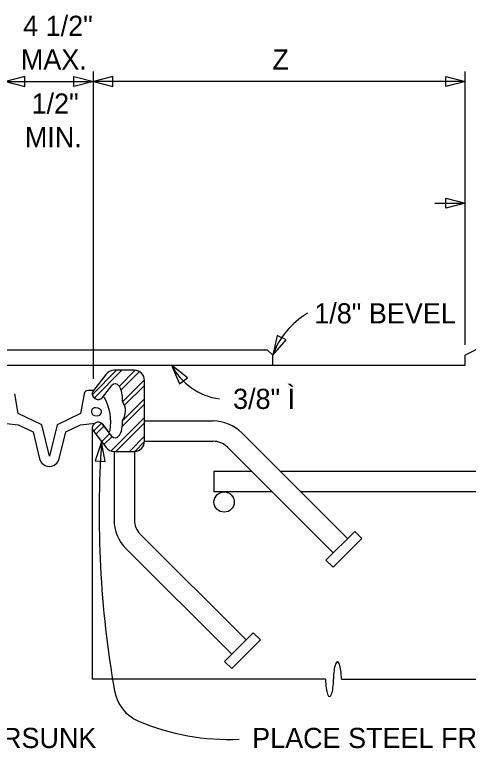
# Model space of a CAD drawing. Extents: x 19590 to 20151, y 19944 to 20103.
# Drawn here: x 19692.57 to 19703.76, y 20061.56 to 20079.66 of the extents above; entities that cross this region are included whole.
import ezdxf

# ---------------------------------------------------------------- set-up
doc = ezdxf.new("R2010")
doc.units = 0
for name, color, linetype in [('DETAIL_PR', 7, 'Continuous'), ('DETAIL_TEXT_DIMEN_PR', 7, 'Continuous'), ('Level 1', 7, 'Continuous')]:
    doc.layers.add(name, color=color, linetype=linetype)

# ---------------------------------------------------------------- blocks, each defined once
blk = doc.blocks.new('BRE')
at = {"layer": 'DETAIL_PR'}
for centre, ratio, start_param, end_param in [((0, 0.098), 0.230206, 4.712389, 7.853982), ((0, -0.098), 0.230204, 1.570796, 4.712389)]:
    blk.add_ellipse(centre, major_axis=(-0.427, 0), ratio=ratio, start_param=start_param, end_param=end_param, dxfattribs=at)

msp = doc.modelspace()

# ---------------------------------------------------------------- linework, layer by layer
at = {"layer": 'DETAIL_PR'}
for p, q in [((19698.811, 20071.384), (19686.436, 20071.384)), ((19698.811, 20071.384), (19686.436, 20071.384)), ((19698.936, 20071.259), (19698.811, 20071.384)), ((19698.936, 20071.259), (19698.811, 20071.384)), ((19704.186, 20071.509), (19703.686, 20071.259)), ((19704.186, 20071.509), (19703.686, 20071.259)), ((19698.936, 20071.009), (19698.936, 20071.259)), ((19698.936, 20071.009), (19698.936, 20071.259)), ((19703.686, 20071.009), (19703.686, 20071.259)), ((19703.686, 20071.009), (19703.686, 20071.259)), ((19686.436, 20071.009), (19698.936, 20071.009)), ((19686.436, 20071.009), (19698.936, 20071.009)), ((19695.444, 20071.009), (19703.686, 20071.009)), ((19695.444, 20071.009), (19703.686, 20071.009)), ((19695.085, 20070.884), (19694.49, 20070.288)), ((19695.085, 20070.884), (19694.49, 20070.288)), ((19695.218, 20070.884), (19694.54, 20070.206)), ((19695.218, 20070.884), (19694.54, 20070.206)), ((19695.526, 20070.884), (19695.026, 20070.884)), ((19695.526, 20070.884), (19695.026, 20070.884)), ((19695.549, 20070.884), (19695.155, 20070.49)), ((19695.549, 20070.884), (19695.155, 20070.49)), ((19695.649, 20070.851), (19695.199, 20070.401)), ((19695.649, 20070.851), (19695.199, 20070.401)), ((19694.828, 20070.787), (19694.515, 20070.384)), ((19694.828, 20070.787), (19694.515, 20070.384)), ((19695.776, 20070.646), (19695.24, 20070.111)), ((19695.776, 20070.646), (19695.24, 20070.111)), ((19694.737, 20070.211), (19694.967, 20070.508)), ((19694.737, 20070.211), (19694.967, 20070.508)), ((19695.776, 20070.513), (19695.284, 20070.021)), ((19695.776, 20070.513), (19695.284, 20070.021)), ((19695.776, 20069.134), (19695.776, 20070.634)), ((19695.776, 20069.134), (19695.776, 20070.634)), ((19692.658, 20069.818), (19692.574, 20070.306)), ((19692.658, 20069.818), (19692.574, 20070.306)), ((19694.285, 20070.306), (19694.201, 20069.818)), ((19694.285, 20070.306), (19694.201, 20069.818)), ((19694.515, 20070.384), (19694.377, 20070.384)), ((19694.515, 20070.384), (19694.377, 20070.384)), ((19694.561, 20070.189), (19694.537, 20070.208)), ((19694.537, 20070.208), (19694.561, 20070.189)), ((19694.561, 20070.189), (19694.537, 20070.208)), ((19694.537, 20070.208), (19694.561, 20070.189)), ((19695.776, 20070.184), (19695.237, 20069.646)), ((19695.776, 20070.184), (19695.237, 20069.646)), ((19694.632, 20069.95), (19694.57, 20069.958)), ((19694.632, 20069.95), (19694.57, 20069.958)), ((19695.776, 20070.052), (19695.231, 20069.507)), ((19695.776, 20070.052), (19695.231, 20069.507)), ((19693.241, 20069.541), (19692.658, 20069.818)), ((19693.241, 20069.541), (19692.658, 20069.818)), ((19694.201, 20069.818), (19693.618, 20069.541)), ((19694.201, 20069.818), (19693.618, 20069.541)), ((19694.545, 20069.772), (19694.607, 20069.764)), ((19694.545, 20069.772), (19694.607, 20069.764)), ((19692.298, 20069.578), (19692.658, 20069.541)), ((19692.298, 20069.578), (19692.658, 20069.541)), ((19694.201, 20069.541), (19694.561, 20069.578)), ((19694.201, 20069.541), (19694.561, 20069.578)), ((19694.711, 20069.581), (19694.514, 20069.384)), ((19694.711, 20069.581), (19694.514, 20069.384)), ((19694.561, 20069.578), (19694.537, 20069.559)), ((19694.561, 20069.578), (19694.537, 20069.559)), ((19695.776, 20069.72), (19694.95, 20068.895)), ((19695.776, 20069.72), (19694.95, 20068.895)), ((19695.776, 20069.588), (19695.072, 20068.884)), ((19695.776, 20069.588), (19695.072, 20068.884)), ((19695.776, 20069.634), (19697.465, 20069.634)), ((19695.776, 20069.634), (19697.465, 20069.634)), ((19692.658, 20069.541), (19693.026, 20069.366)), ((19692.658, 20069.541), (19693.026, 20069.366)), ((19693.429, 20068.762), (19693.241, 20069.541)), ((19693.429, 20068.762), (19693.241, 20069.541)), ((19693.618, 20069.541), (19693.429, 20068.762)), ((19693.618, 20069.541), (19693.429, 20068.762)), ((19693.833, 20069.366), (19694.201, 20069.541)), ((19693.833, 20069.366), (19694.201, 20069.541)), ((19694.488, 20069.454), (19694.488, 20063.262)), ((19694.488, 20069.454), (19694.488, 20063.262)), ((19694.515, 20069.384), (19694.828, 20068.98)), ((19694.515, 20069.384), (19694.828, 20068.98)), ((19694.772, 20069.51), (19694.572, 20069.31)), ((19694.772, 20069.51), (19694.572, 20069.31)), ((19694.737, 20069.556), (19694.87, 20069.385)), ((19694.967, 20069.26), (19694.737, 20069.556)), ((19694.737, 20069.556), (19694.87, 20069.385)), ((19694.967, 20069.26), (19694.737, 20069.556)), ((19693.026, 20069.366), (19693.186, 20068.703)), ((19693.026, 20069.366), (19693.186, 20068.703)), ((19693.672, 20068.703), (19693.833, 20069.366)), ((19693.672, 20068.703), (19693.833, 20069.366)), ((19694.917, 20069.324), (19694.717, 20069.123)), ((19694.917, 20069.324), (19694.717, 20069.123)), ((19694.974, 20069.251), (19694.774, 20069.05)), ((19694.974, 20069.251), (19694.774, 20069.05)), ((19695.776, 20069.256), (19695.403, 20068.884)), ((19695.776, 20069.256), (19695.403, 20068.884)), ((19698.172, 20069.341), (19700.781, 20066.732)), ((19698.172, 20069.341), (19700.781, 20066.732)), ((19695.776, 20069.124), (19695.536, 20068.884)), ((19695.776, 20069.124), (19695.536, 20068.884)), ((19695.776, 20069.134), (19697.465, 20069.134)), ((19695.776, 20069.134), (19697.465, 20069.134)), ((19695.026, 20068.884), (19695.526, 20068.884)), ((19695.026, 20068.884), (19695.026, 20067.194)), ((19695.026, 20068.884), (19695.526, 20068.884)), ((19695.026, 20068.884), (19695.026, 20067.194)), ((19695.526, 20068.884), (19695.526, 20067.194)), ((19695.526, 20068.884), (19695.526, 20067.194)), ((19697.818, 20068.987), (19700.427, 20066.378)), ((19697.818, 20068.987), (19700.427, 20066.378)), ((19698.422, 20068.384), (19697.488, 20068.384)), ((19697.488, 20068.384), (19697.488, 20067.884)), ((19698.422, 20068.384), (19697.488, 20068.384)), ((19697.488, 20068.384), (19697.488, 20067.884)), ((19708.186, 20068.384), (19699.129, 20068.384)), ((19708.186, 20068.384), (19699.129, 20068.384)), ((19698.922, 20067.884), (19697.488, 20067.884)), ((19698.922, 20067.884), (19697.488, 20067.884)), ((19708.186, 20067.884), (19699.629, 20067.884)), ((19708.186, 20067.884), (19699.629, 20067.884)), ((19700.958, 20066.909), (19700.25, 20066.202)), ((19700.958, 20066.909), (19700.25, 20066.202)), ((19700.958, 20066.909), (19701.134, 20066.732)), ((19700.958, 20066.909), (19701.134, 20066.732)), ((19695.672, 20066.841), (19698.281, 20064.232)), ((19695.672, 20066.841), (19698.281, 20064.232)), ((19701.134, 20066.732), (19700.427, 20066.025)), ((19701.134, 20066.732), (19700.427, 20066.025)), ((19695.318, 20066.487), (19697.927, 20063.878)), ((19695.318, 20066.487), (19697.927, 20063.878)), ((19700.25, 20066.202), (19700.427, 20066.025)), ((19700.25, 20066.202), (19700.427, 20066.025)), ((19698.458, 20064.409), (19697.75, 20063.702)), ((19698.458, 20064.409), (19697.75, 20063.702)), ((19698.458, 20064.409), (19698.634, 20064.232)), ((19698.458, 20064.409), (19698.634, 20064.232)), ((19698.634, 20064.232), (19697.927, 20063.525)), ((19698.634, 20064.232), (19697.927, 20063.525)), ((19697.75, 20063.702), (19697.927, 20063.525)), ((19697.75, 20063.702), (19697.927, 20063.525))]:
    msp.add_line(p, q, dxfattribs=at)
msp.add_circle((19697.738, 20067.634), 0.25, dxfattribs=at)
msp.add_circle((19697.738, 20067.634), 0.25, dxfattribs=at)
for centre, radius, start, end in [((19695.026, 20070.634), 0.25, 90, 142.143), ((19695.026, 20070.634), 0.25, 90, 142.143), ((19695.526, 20070.634), 0.25, 0, 90), ((19695.526, 20070.634), 0.25, 0, 90), ((19694.377, 20070.29), 0.0938, 90, 170.2238), ((19694.377, 20070.29), 0.0938, 90, 170.2238), ((19694.613, 20070.307), 0.125, 142.143, 232.143), ((19694.613, 20070.307), 0.125, 142.143, 232.143), ((19694.613, 20070.307), 0.125, 142.143, 232.143), ((19694.613, 20070.307), 0.125, 142.143, 232.143), ((19694.638, 20070.288), 0.125, 232.143, 322.143), ((19694.638, 20070.288), 0.125, 232.143, 322.143), ((19694.638, 20070.288), 0.125, 232.143, 321.3779), ((19694.638, 20070.288), 0.125, 232.143, 321.3779), ((19694.76, 20070.19), 0.0312, 29.2634, 141.3779), ((19694.76, 20070.19), 0.0312, 29.2634, 141.3779), ((19693.72, 20069.607), 1.224, 350.1703, 29.2634), ((19693.72, 20069.607), 1.224, 350.1703, 29.2634), ((19694.888, 20069.884), 0.419, 325.0258, 33.6795), ((19694.888, 20069.884), 0.419, 325.0258, 33.6795), ((19694.558, 20069.865), 0.0938, 82.4005, 170.2238), ((19694.558, 20069.865), 0.0938, 82.4005, 170.2238), ((19694.62, 20069.857), 0.0938, 350.2238, 82.4005), ((19694.62, 20069.857), 0.0938, 350.2238, 82.4005), ((19694.558, 20069.865), 0.0937, 170.2238, 262.4005), ((19694.558, 20069.865), 0.0937, 170.2238, 262.4005), ((19694.62, 20069.857), 0.0938, 262.4005, 350.2238), ((19694.62, 20069.857), 0.0938, 262.4005, 350.2238), ((19694.613, 20069.46), 0.125, 127.857, 217.857), ((19694.613, 20069.46), 0.125, 127.857, 217.857), ((19694.638, 20069.48), 0.125, 37.857, 127.857), ((19694.638, 20069.48), 0.125, 37.857, 127.857), ((19694.638, 20069.48), 0.125, 37.857, 127.857), ((19694.638, 20069.48), 0.125, 37.857, 127.857), ((19697.465, 20068.634), 1, 45, 90), ((19697.465, 20068.634), 1, 45, 90), ((19694.895, 20069.404), 0.0312, 217.857, 350.1703), ((19694.895, 20069.404), 0.0312, 217.857, 350.1703), ((19695.526, 20069.134), 0.25, 270, 360), ((19695.526, 20069.134), 0.25, 270, 360), ((19697.465, 20068.634), 0.5, 45, 90), ((19697.465, 20068.634), 0.5, 45, 90), ((19695.026, 20069.134), 0.25, 217.857, 270), ((19695.026, 20069.134), 0.25, 217.857, 270), ((19693.429, 20068.762), 0.25, 193.5864, 346.4136), ((19693.429, 20068.762), 0.25, 193.5864, 346.4136), ((19696.026, 20067.194), 1, 180, 225), ((19696.026, 20067.194), 1, 180, 225), ((19696.026, 20067.194), 0.5, 180, 225), ((19696.026, 20067.194), 0.5, 180, 225)]:
    msp.add_arc(centre, radius, start, end, dxfattribs=at)
for centre, major_axis, start_param, end_param in [((19695.042, 20070.127), (-0.016, -0.425), 1.562431, 3.622562), ((19695.042, 20070.127), (-0.016, -0.425), 1.562431, 3.622562), ((19695.042, 20069.64), (0.016, -0.425), 5.802216, 7.862347), ((19695.042, 20069.64), (0.016, -0.425), 5.802216, 7.862347)]:
    msp.add_ellipse(centre, major_axis=major_axis, ratio=0.457019, start_param=start_param, end_param=end_param, dxfattribs=at)
at = {"layer": 'DETAIL_TEXT_DIMEN_PR'}
for p, q in [((19694.515, 20070.676), (19694.515, 20078.259)), ((19694.515, 20070.676), (19694.515, 20078.259)), ((19703.686, 20071.509), (19703.686, 20078.259)), ((19703.686, 20071.509), (19703.686, 20078.259)), ((19692.826, 20078.133), (19692.344, 20078.009)), ((19692.826, 20078.133), (19692.344, 20078.009)), ((19692.826, 20077.884), (19692.826, 20078.133)), ((19692.826, 20077.884), (19692.826, 20078.133)), ((19694.033, 20078.133), (19694.515, 20078.009)), ((19694.033, 20077.884), (19694.033, 20078.133)), ((19694.033, 20078.133), (19694.515, 20078.009)), ((19694.033, 20077.884), (19694.033, 20078.133)), ((19694.996, 20078.133), (19694.515, 20078.009)), ((19694.996, 20078.133), (19694.515, 20078.009)), ((19694.996, 20077.884), (19694.996, 20078.133)), ((19694.996, 20077.884), (19694.996, 20078.133)), ((19703.204, 20078.133), (19703.686, 20078.009)), ((19703.204, 20077.884), (19703.204, 20078.133)), ((19703.204, 20078.133), (19703.686, 20078.009)), ((19703.204, 20077.884), (19703.204, 20078.133)), ((19692.344, 20078.009), (19694.515, 20078.009)), ((19692.344, 20078.009), (19692.826, 20077.884)), ((19692.344, 20078.009), (19694.515, 20078.009)), ((19692.344, 20078.009), (19692.826, 20077.884)), ((19694.515, 20078.009), (19694.033, 20077.884)), ((19694.515, 20078.009), (19694.033, 20077.884)), ((19703.686, 20078.009), (19694.515, 20078.009)), ((19694.515, 20078.009), (19694.996, 20077.884)), ((19703.686, 20078.009), (19694.515, 20078.009)), ((19694.515, 20078.009), (19694.996, 20077.884)), ((19703.686, 20078.009), (19703.204, 20077.884)), ((19703.686, 20078.009), (19703.204, 20077.884)), ((19703.204, 20075.133), (19703.686, 20075.009)), ((19703.204, 20074.884), (19703.204, 20075.133)), ((19703.204, 20075.133), (19703.686, 20075.009)), ((19703.204, 20074.884), (19703.204, 20075.133)), ((19703.686, 20075.009), (19703.204, 20074.884)), ((19703.686, 20075.009), (19703.204, 20074.884)), ((19699.043, 20071.745), (19698.936, 20071.259)), ((19699.043, 20071.745), (19698.936, 20071.259)), ((19699.265, 20071.632), (19699.043, 20071.745)), ((19699.265, 20071.632), (19699.043, 20071.745)), ((19698.936, 20071.259), (19699.265, 20071.632)), ((19698.936, 20071.259), (19699.265, 20071.632)), ((19696.833, 20070.699), (19696.443, 20071.009)), ((19696.443, 20071.009), (19696.635, 20070.549)), ((19696.833, 20070.699), (19696.443, 20071.009)), ((19696.443, 20071.009), (19696.635, 20070.549)), ((19696.635, 20070.549), (19696.833, 20070.699)), ((19696.635, 20070.549), (19696.833, 20070.699)), ((19694.717, 20069.123), (19694.558, 20068.652)), ((19694.717, 20069.123), (19694.558, 20068.652)), ((19694.806, 20068.634), (19694.717, 20069.123)), ((19694.806, 20068.634), (19694.717, 20069.123)), ((19694.558, 20068.652), (19694.806, 20068.634)), ((19694.558, 20068.652), (19694.806, 20068.634)), ((19700.239, 20063.262), (19694.488, 20063.262)), ((19700.239, 20063.262), (19694.488, 20063.262)), ((19700.632, 20063.262), (19708.686, 20063.262)), ((19700.632, 20063.262), (19708.686, 20063.262))]:
    msp.add_line(p, q, dxfattribs=at)
for centre, radius, start, end in [((19720.068, 20067.36), 25.412, 176.0213, 189.9305), ((19720.068, 20067.36), 25.412, 176.0213, 189.9305), ((19696.021, 20063.15), 1, 189.9305, 246.7533), ((19696.021, 20063.15), 1, 189.9305, 246.7533), ((19697.832, 20067.364), 5.586, 246.7533, 272.8645), ((19697.832, 20067.364), 5.586, 246.7533, 272.8645)]:
    msp.add_arc(centre, radius, start, end, dxfattribs=at)
at = {"layer": 'Level 1'}
msp.add_line((19702.936, 20075.009), (19703.686, 20075.009), dxfattribs=at)
msp.add_line((19702.936, 20075.009), (19703.686, 20075.009), dxfattribs=at)
for centre, radius, start, end in [((19700.831, 20070.554), 2.022, 120.8358, 159.6044), ((19700.831, 20070.554), 2.022, 120.8358, 159.6044), ((19697.832, 20071.732), 1.566, 207.5156, 262.4161), ((19697.832, 20071.732), 1.566, 207.5156, 262.4161)]:
    msp.add_arc(centre, radius, start, end, dxfattribs=at)

# ---------------------------------------------------------------- block references
at = {"layer": 'Level 1', "rotation": 90}
msp.add_blockref('BRE', (19700.436, 20063.262), dxfattribs=at)
msp.add_blockref('BRE', (19700.436, 20063.262), dxfattribs=at)

# ---------------------------------------------------------------- texts
at = {"layer": 'DETAIL_TEXT_DIMEN_PR'}
for s, height, p in [('4 1/2"', 0.4976, (19692.783, 20079.133)), ('4 1/2"', 0.4976, (19692.783, 20079.133)), ('MAX.', 0.4976, (19692.726, 20078.304)), ('MAX.', 0.4976, (19692.726, 20078.304)), ('Z', 0.498, (19698.93, 20078.302)), ('Z', 0.498, (19698.93, 20078.302)), ('1/2"', 0.4976, (19692.991, 20077.216)), ('1/2"', 0.4976, (19692.991, 20077.216)), ('MIN.', 0.4976, (19692.825, 20076.387)), ('MIN.', 0.4976, (19692.825, 20076.387)), ('1/8" BEVEL', 0.4976, (19699.961, 20072.041)), ('1/8" BEVEL', 0.4976, (19699.961, 20072.041)), ('3/8" Ì', 0.4976, (19697.959, 20069.931)), ('3/8" Ì', 0.4976, (19697.959, 20069.931)), ('FLATHEAD COUNTERSUNK', 0.49762, (19685.79, 20061.566)), ('FLATHEAD COUNTERSUNK', 0.49762, (19685.79, 20061.566)), ('PLACE STEEL FRAME 1/8" ', 0.49762, (19698.429, 20061.566)), ('PLACE STEEL FRAME 1/8" ', 0.49762, (19698.429, 20061.566))]:
    msp.add_text(s, height=height, dxfattribs=at).set_placement(p)

doc.saveas('drawing.dxf')
